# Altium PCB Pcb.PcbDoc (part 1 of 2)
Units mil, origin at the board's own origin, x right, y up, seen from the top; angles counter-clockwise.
Board outline 4875.67 x 2076.77 mil, 2 copper layers (Top Layer, Bottom Layer), stack 55.6 mil thick; 76 components, 37 nets, 162 pads, 28 vias.
Unrouted connection lines stored in the file: 67.
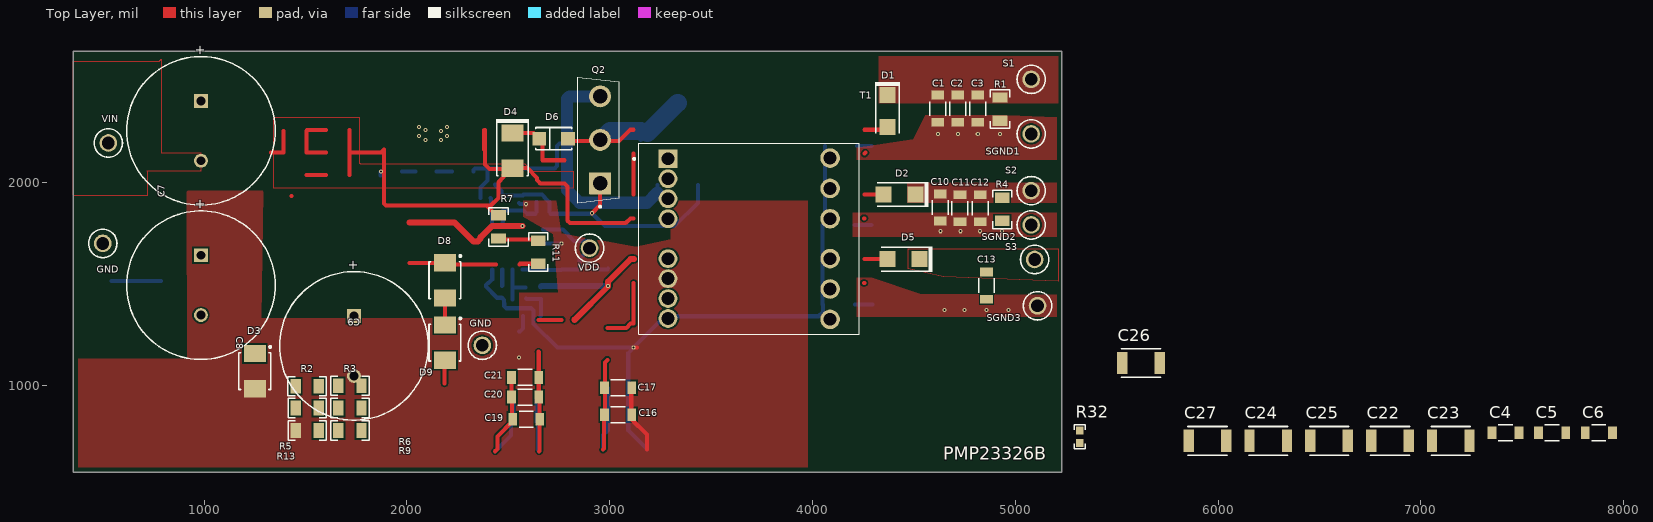
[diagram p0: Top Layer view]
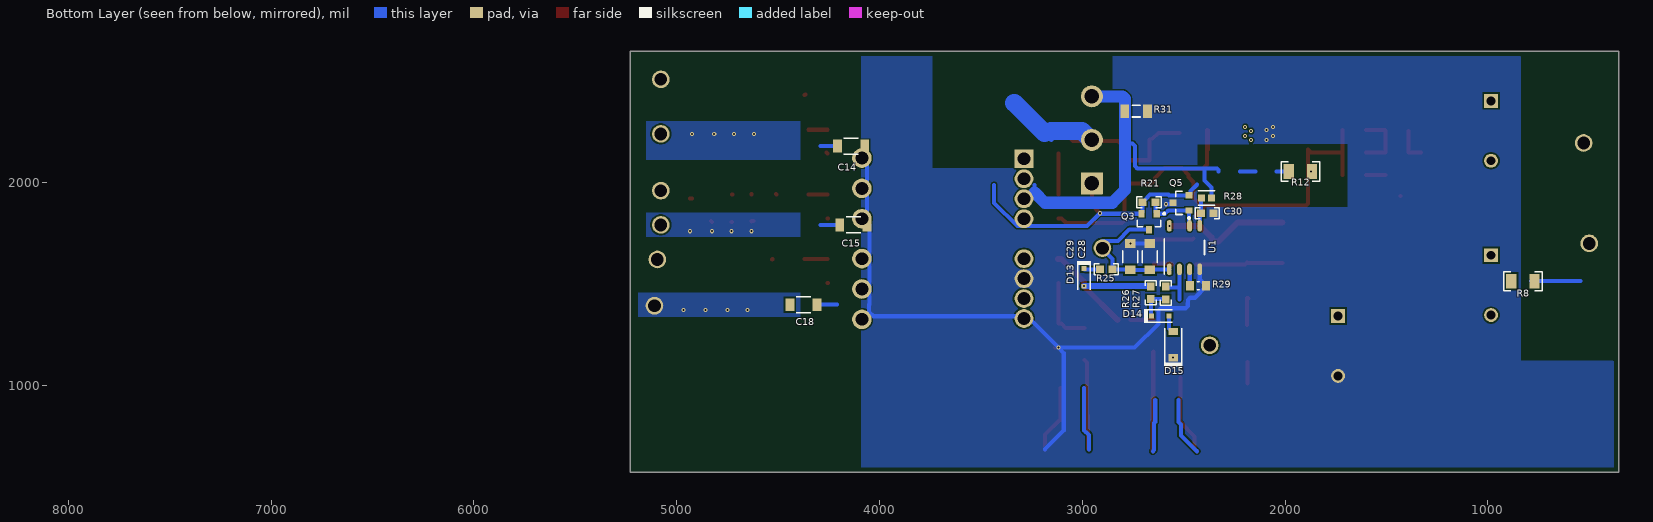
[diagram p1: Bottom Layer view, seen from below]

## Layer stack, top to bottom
Top Solder: solder mask 0.4, Solder Resist, Dk 3.5
Top Layer: signal copper 2.8
Dielectric 1: core 14.2, FR-4, Dk 4.8
Dielectric1: prepreg 21.6, Dk 4.2
Dielectric 2: core 14.2, FR-4, Dk 4.8
Bottom Layer: signal copper 2.8
Bottom Solder: solder mask 0.4, Solder Resist, Dk 3.5

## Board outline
354.33,570.87 5230,570.87 5230,2647.64 354.33,2647.64

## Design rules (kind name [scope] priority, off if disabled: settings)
AcuteAngle [All] p1: minimum=4.50000000000000E+0001 checktracksonly=FALSE
AssemblyTestPointUsage [All] p1: valid=2
BoardOutlineClearance BoardOutlineClearance_MountingHoles [OnCopper and InComponentClass('Mounting Holes')] p1: gap=39.37 ignorepadtopadclearanceinfootprint=FALSE
BoardOutlineClearance BoardOutlineClearance_Poly [OnCopper and IsPoly] p2: gap=25 ignorepadtopadclearanceinfootprint=FALSE
BoardOutlineClearance [OnCopper and Not InComponentClass('Logo') and not InComponentClass('FiducialMark') and not InRegion(1000,500,4000,800) and not InPoly] p3: gap=75 ignorepadtopadclearanceinfootprint=FALSE
Clearance [InNet('HV_plus') vs InNet('HV_minus')] p1: gap=140 ignorepadtopadclearanceinfootprint=TRUE
Clearance Clearance_3 [All] p2: gap=7.87 ignorepadtopadclearanceinfootprint=TRUE
Clearance Clearance_2 [InNet('SGND1') vs InNet('SGND2')] p3: gap=150 ignorepadtopadclearanceinfootprint=TRUE
Clearance Clearance_1 [InNet('SGND2') vs InNet('SGND3')] p4: gap=150 ignorepadtopadclearanceinfootprint=TRUE
Clearance Clearance_Keepouts [((IsTrack Or IsArc) And Not InPoly) And IsFree and IsKeepOut vs ((IsTrack Or IsArc) And Not InPoly) And IsFree and IsKeepOut] p5: gap=0 ignorepadtopadclearanceinfootprint=FALSE
Clearance Clearance_Poly [InPolygon] p6: gap=25 ignorepadtopadclearanceinfootprint=TRUE
Clearance Clearance_FiducialMark [IsKeepOut and InComponentClass('FiducialMark') vs IsPad and InComponentClass('FiducialMark')] p7: gap=0 ignorepadtopadclearanceinfootprint=FALSE
Clearance Clearance-pgnd-vin [InNet('PGND') vs InNet('NetC7_1')] p8: gap=120 ignorepadtopadclearanceinfootprint=TRUE
ComponentClearance ComponentClearance_MountingHoles_FiducialMarks [InComponentClass('Mounting Holes') vs InComponentClass('FiducialMark')] p1: gap=50 collisioncheckmode=3 verticalgap=10 showdistances=FALSE
ComponentClearance ComponentClearance_Shunt [InComponentClass('Header') vs InComponentClass('Shunt')] p2: gap=0 collisioncheckmode=3 verticalgap=0 showdistances=FALSE
ComponentClearance ComponentClearance_Logo [InComponentClass('Logo')] p3: gap=50 collisioncheckmode=3 verticalgap=10 showdistances=FALSE
ComponentClearance ComponentClearance_ScrewToNut [(HasFootprint('NY PMS 440 0025 PH')) vs (HasFootprint('Keystone_1902C'))] p4: gap=5 collisioncheckmode=3 verticalgap=10 showdistances=FALSE
ComponentClearance ComponentClearance_MountingHoles [InComponentClass('Mounting Holes')] p5: gap=250 collisioncheckmode=3 verticalgap=100000 showdistances=FALSE
ComponentClearance ComponentClearance_SmallPassives [HasFootprint('0201*') or HasFootprint('0402*') or HasFootprint('0508') or HasFootprint('0603*') or HasFootprint('0612') or HasFootprint('0805*') or HasFootprint('0815*') or HasFootprint('0830*') or HasFootprint('1206*') or HasFootprint('1210*') or HasFootprint('1808*') or HasFootprint('1812*') or HasFootprint('1825*') or HasFootprint('2010*') or HasFootprint('2220*') or HasFootprint('2225*') or HasFootprint('2512*') or HasFootprint('2728*') or HasFootprint('3518*') vs HasFootprint('0201*') or HasFootprint('0402*') or HasFootprint('0508') or HasFootprint('0603*') or HasFootprint('0612') or HasFootprint('0805*') or HasFootprint('0815*') or HasFootprint('0830*') or HasFootprint('1206*') or HasFootprint('1210*') or HasFootprint('1808*') or HasFootprint('1812*') or HasFootprint('1825*') or HasFootprint('2010*') or HasFootprint('2220*') or HasFootprint('2225*') or HasFootprint('2512*') or HasFootprint('2728*') or HasFootprint('3518*')] p6: gap=14.96 collisioncheckmode=3 verticalgap=10 showdistances=FALSE
ComponentClearance ComponentClearance_THtoSMT [IsThruComponent vs IsSMTComponent] p7: gap=40 collisioncheckmode=3 verticalgap=30 showdistances=FALSE
ComponentClearance ComponentClearance_THtoTH [IsThruComponent vs IsThruComponent] p8: gap=30 collisioncheckmode=3 verticalgap=30 showdistances=FALSE
ComponentClearance [All] p9: gap=30 collisioncheckmode=3 verticalgap=10 showdistances=FALSE
DiffPairsRouting [All] p1: maxlimit=100 minlimit=10 mostfreqgap=10 toplayer_minwidth=15 toplayer_maxwidth=15 toplayer_prefwidth=15 bottomlayer_minwidth=15 bottomlayer_maxwidth=15 bottomlayer_prefwidth=15 maxuncoupledlength=1000
FabricationTestPointUsage TestPointUsage [All] p1: valid=2 allowmultiple=FALSE
FabricationTestpoint Testpoint [All] p1: side=3 testpointundercomponent=TRUE minsize=40 maxsize=100 preferedsize=60 minholesize=0 maxholesize=40 preferedholesize=32 testpointgrid=1 allowsidetop=TRUE allowsidebottom=TRUE usegrid=TRUE gridtolerance=0.01
FanoutControl Fanout_LCC [IsLCC] p1: bgadir=Out bgaviamode=Centered fanoutstyle=Auto fanoutdirection=Alternating viagrid=1 // Fanout_LCC (Default Rule)
FanoutControl Fanout_BGA [IsBGA] p2: bgadir=Out bgaviamode=Centered fanoutstyle=Auto fanoutdirection=Alternating viagrid=1 // Fanout_BGA (Default Rule)
FanoutControl Fanout_Default [All] p4: bgadir=Out bgaviamode=Centered fanoutstyle=Auto fanoutdirection=Alternating viagrid=1 // Fanout_Default (Default Rule)
FanoutControl Fanout_Small [(CompPinCount < 5)] p5: bgadir=Out bgaviamode=Centered fanoutstyle=Auto fanoutdirection=OutThenIn viagrid=1 // Fanout_Small (Default Rule)
HoleSize [All] p1: absolutevalues=TRUE maxlimit=251 minlimit=7.87 maxpercent=80.000 minpercent=20.000
MinimumAnnularRing MinimumAnnularRing_ThermalPadVias [IsVia and InAnyComponent] p1: minimumring=5.91
MinimumAnnularRing [All] p2: minimumring=4.5
MinimumSolderMaskSliver MinimumSolderMaskSliver_Logo [InComponentClass('Logo') vs InComponentClass('Logo')] p1: minsoldermaskwidth=0.7
MinimumSolderMaskSliver [All] p2: minsoldermaskwidth=3.94
PlaneConnect [All] p1: planeconnectstyle=Direct reliefexpansion=10 reliefentries=4 reliefconductorwidth=10 reliefairgap=10
PolygonConnect [All] p1: connectstyle=Direct reliefconductorwidth=10 reliefentries=4 polygonreliefangle="90 Angle" airgapwidth=10
RoutingVias ThermalPadVias [IsVia and InAnyComponent] p1: holewidth=7.87 width=19.68 viastyle="Through Hole" minholewidth=7.87 minwidth=19.68 maxholewidth=12.99 maxwidth=23.62
RoutingVias [All] p2: holewidth=16 width=34 viastyle="Through Hole" minholewidth=7.87 minwidth=18 maxholewidth=40 maxwidth=65
SilkToBoardRegionClearance [Not ((IsComment or IsDesignator) And (Hide <> 'False')) and not InRegion(1000,500,4000,800)] p1:
SilkToSilkClearance SilkToSilkClearance_Pb-FreeLogo [(HasFootprint('Pb-Free_Overlay_Medium') OR HasFootprint('Pb-Free_Overlay_Small')) vs (HasFootprint('Pb-Free_Overlay_Medium') OR HasFootprint('Pb-Free_Overlay_Small'))] p1: silktosilkclearance=0
SilkToSilkClearance [All] p2: silktosilkclearance=3.94
SilkToSolderMaskClearance SilkToComponentPadClearance [(IsPad or IsFill or IsRegion) and InAnycomponent] p1: minsilkscreentomaskgap=5 clearancetoexposedcopper=TRUE
SilkToSolderMaskClearance "Silk to Solder Mask Opening" [All] p2: minsilkscreentomaskgap=3.94 clearancetoexposedcopper=FALSE
SolderMaskExpansion [All] p1: expansion=1.97 istentingtop=FALSE
UnRoutedNet [All] p1: checkbadconnections=TRUE
Width [All] p1: maxlimit=100 minlimit=6 preferedwidth=20 minimp=50.000000 maximp=50.000000 favimp=50.000000 checkconnectedcopper=TRUE
14 further rules are at their usual default settings.

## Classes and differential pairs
component class Schematic: C1 C2 C3 C7 C8 C9 C13 C14 C15 C16 C17 C18 C19 C20 C21 C25 C26 C27 C28 C29 C30 D1 D2 D3 D4 D5 D6 D8 D9 D13 D14 D15 Q2 Q3 Q5 R1 R2 R3 R4 R5 R6 R7 R8 R9 R11 R12 R13 R21 R25 R26 R27 R28 R29 R31 R32 S1 S2 S3 SGND1 SGND2 SGND3 T1 U1 VDD VIN

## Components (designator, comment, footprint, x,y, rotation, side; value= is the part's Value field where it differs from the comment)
C1 "UMJ316AB7225KLHT" 1206_180 4618.38,2364.32 r270 top value=2.2uF
C2 "UMJ316AB7225KLHT" 1206_180 4716.81,2364.32 r270 top value=2.2uF
C3 "UMJ316AB7225KLHT" 1206_180 4815.23,2364.32 r270 top value=2.2uF
C4 "UMJ316AB7225KLHT" 1206_180 7418,766 r0 top value=2.2uF
C5 "UMJ316AB7225KLHT" 1206_180 7648,766 r0 top value=2.2uF
C6 "UMJ316AB7225KLHT" 1206_180 7878,766 r0 top value=2.2uF
C7 "EEU-EE2G470S" EE_1800x2000 984.01,2255.18 r270 top value=47uF
C8 "EEU-EE2G470S" EE_1800x2000 984.01,1493.93 r270 top value=47uF
C9 "EEU-EE2G470S" EE_1800x2000 1738.47,1194.29 r270 top value=47uF
C10 "UMJ316AB7225KLHT" 1206_180 4630.46,1877.16 r270 top value=2.2uF
C11 "UMJ316AB7225KLHT" 1206_180 4727.49,1873.33 r270 top value=2.2uF
C12 "UMJ316AB7225KLHT" 1206_180 4827.31,1873.33 r270 top value=2.2uF
C13 "UMJ316AB7225KLHT" 1206_180 4858.36,1491.68 r270 top value=2.2uF
C14 "UMJ316AB7225KLHT" 1206_180 4140,2180 r180 bottom value=2.2uF
C15 "UMJ316AB7225KLHT" 1206_180 4128.74,1791.34 r180 bottom value=2.2uF
C16 "UMJ316AB7225KLHT" 1206_180 3041.34,855.41 r0 top value=2.2uF
C17 "UMJ316AB7225KLHT" 1206_180 3041.34,987.84 r0 top value=2.2uF
C18 "UMJ316AB7225KLHT" 1206_180 4374.9,1397.64 r180 bottom value=2.2uF
C19 "UMJ316AB7225KLHT" 1206_180 2588.56,832.67 r180 top value=2.2uF
C20 "UMJ316AB7225KLHT" 1206_180 2583.1,942.31 r180 top value=2.2uF
C21 "UMJ316AB7225KLHT" 1206_180 2583.1,1039.2 r180 top value=2.2uF
C22 "C4532X7R3D222K130KA" FP-C4532-130-MFG 6848,726 r0 top
C23 "C4532X7R3D222K130KA" FP-C4532-130-MFG 7148,726 r0 top
C24 "C4532X7R3D222K130KA" FP-C4532-130-MFG 6248,726 r0 top
C25 "C4532X7R3D222K130KA" FP-C4532-130-MFG 6548,726 r0 top
C26 "C4532X7R3D222K130KA" FP-C4532-130-MFG 5620,1110 r0 top
C27 "C4532X7R3D222K130KA" FP-C4532-130-MFG 5948,726 r0 top
C28 "" FP-CGA5L-0_3-0_1-MFG 2667.11,1634.48 r90 bottom
C29 "" FP-CGA5L-0_3-0_1-MFG 2763.13,1634.48 r90 bottom
C30 "CGA3E2NP01H101J080AA" 0603 2383.53,1848.64 r180 bottom value=100pF
D1 "MURA160T3G" SMA 4369.44,2352.36 r270 top value=600V
D2 "MURA160T3G" SMA 4429.13,1941.67 r180 top value=600V
D3 "SZ1SMB5956BT3G" ONSC-SMB-2-403A-03_H_V 1250,1070 r270 top
D4 "SMBJ100A-13-F" SMB 2520.8,2157.78 r270 top value=100V
D5 "MURA160T3G" SMA 4448.82,1622.13 r180 top value=600V
D6 "BYG23T-M3/TR" FP-SMA-MFG 2723.85,2216.63 r0 top
D8 "SZ1SMB5956BT3G" ONSC-SMB-2-403A-03_H_V 2187.57,1518.05 r270 top
D9 "SZ1SMB5956BT3G" ONSC-SMB-2-403A-03_H_V 2187.57,1210.63 r270 top
D13 "BAV20WS-TP" SOD-323 2991.61,1532.28 r270 bottom value=150V
D14 "BAV20WS-TP" SOD-323 2615.69,1341.92 r180 bottom value=150V
D15 "DDZ20CQ-7" SOD-123 2552.03,1200.79 r90 bottom value=20V
GND "5011" Keystone5011 500,1700 r90 top
GND "5011" Keystone5011 2371.72,1197.49 r0 top
Q2 "STW12N120K5" FP-STW12N120K5_TO-247-3-MFG 2944.88,2210.52 r180 top
Q3 "MMBT3904LT1G" ONSC-SOT-23-3-318-08_V 2670.89,1806.91 r270 bottom
Q5 "MMBT2907ALT3G" ONSC-SOT-23-3-318-08_V 2512.66,1899.83 r0 bottom
R1 "ERJ-8ENF1002V" 1206 4924.75,2362.2 r90 top value=10.0k
R2 "CRCW1206470KJNEA" 1206 1507.87,995.34 r0 top value=470k
R3 "ERJ-8ENF1002V" 1206 1718.78,998.27 r0 top value=10.0k
R4 "ERJ-8ENF1002V" 1206 4935.58,1867.86 r90 top value=10.0k
R5 "CRCW1206470KJNEA" 1206 1508.19,887.53 r0 top value=470k
R6 "CRCW1206300KJNEA" 1206 1718.78,887.53 r0 top value=300k
R7 "CRCW1206300KJNEA" 1206 2451.52,1780.97 r90 top value=300k
R8 "CRCW1206470KJNEA" 1206 826.77,1513.61 r0 bottom value=470k
R9 "CRCW1206300KJNEA" 1206 1718.78,777.04 r0 top value=300k
R11 "CRCW1206470KJNEA" 1206 2647.26,1656.8 r90 top value=470k
R12 "CRCW1206470KJNEA" 1206 1924.21,2054.7 r180 bottom value=470k
R13 "CRCW1206470KJNEA" 1206 1508.19,777.04 r0 top value=470k
R21 "RMCF0603ZT0R00" 0603 2670.89,1903.52 r0 bottom value=0
R25 "RMCF0603ZT0R00" 0603 2881.91,1572.07 r180 bottom value=0
R26 "ERJ3EKF5601V" 0603 2662.19,1456.33 r90 bottom value=5.60k
R27 "ERA-3AEB3742V" 0603 2588.05,1455.35 r270 bottom value=37.4k
R28 "1.2k" FP-ERA3A-IPC_C 2387.46,1923.41 r180 bottom
R29 "332k" FP-RG1608-MFG 2428.8,1490.49 r0 bottom
R31 "1.5" RESC3216X70X50NL05T20 2734.63,2351.9 r0 bottom
R32 "CRCW060313K3FKEA" 0603 5318,746 r90 top value=13.3k
S1 "5010" Keystone5010 5078.74,2509.08 r0 top
S2 "5010" Keystone5010 5078.74,1960 r0 top
S3 "5010" Keystone5010 5095.81,1620.72 r0 top
SGND1 "5011" Keystone5011 5078.74,2240 r0 top
SGND2 "5011" Keystone5011 5078.74,1791.34 r0 top
SGND3 "5011" Keystone5011 5110,1392.41 r0 top
T1 "750320469" FP-750320469_PTH14-MFG 3687.32,1723.17 r0 top
U1 "UCC28730QDRQ1" D0007A_N 2495.73,1679.36 r90 bottom
VDD "5010" Keystone5010 2900.61,1676.48 r0 top
VIN "5010" Keystone5010 527.33,2195.17 r90 top

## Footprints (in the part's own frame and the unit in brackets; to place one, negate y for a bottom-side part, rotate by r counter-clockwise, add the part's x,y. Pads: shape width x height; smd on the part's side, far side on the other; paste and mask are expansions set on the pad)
0603 [mm] "0603 from SM-752 data"
  rect 1x0.95 smd: 1(-0.8,0) 2(0.8,0)
  silkscreen extent -1.52,-0.69 1.52,0.69, body extent -0.87,-0.47 0.87,0.47, height 1
1206 [mm] "1206 from SM-752 data"
  rect 1.3x1.85 smd: 1(-1.45,0) 2(1.45,0)
  silkscreen extent -2.4,-1.21 2.4,1.21, body extent -1.7,-0.9 1.7,0.9, height 1.35
1206_180 [mm] "1206_180"
  rect 1.1x1.6 smd: 1(-1.7,0) 2(1.7,0)
  silkscreen extent -0.9,-1 0.9,1, body extent -1.75,-0.95 1.75,0.95, height 1.8
D0007A_N [mm] "SOIC, 7-Leads, Body 4.9x3.9mm, Pitch 1.27mm, IPC Medium Density"
  oval 1.45x0.6 smd: 1(-2.725,1.905) 2(-2.725,0.635) 3(-2.725,-0.635) 4(-2.725,-1.905) 5(2.725,-1.905) 6(2.725,-0.635) 8(2.725,1.905)
  silkscreen extent -3.32,-2.5 1.1,2.52, body extent -3.01,-2.45 3.01,2.45, height 1.75
EE_1800x2000 [mm] "PANASONIC"
  rect 1.75x1.75 hole 1.1: 1(-3.75,0)
  round 1.75 hole 1.1: 2(3.75,0)
  silkscreen extent -9.3,-9.3 9.3,9.3, body extent -9.18,-9.23 9.22,9.24, height 22.01
FP-750320469_PTH14-MFG [mm]
  rrect4% 2.35x2.35 hole 1.6 paste-1000 mask+0: 1(-10.15,10)
  round 2.35 hole 1.6 paste-1000 mask+0: 2(-10.15,7.5) 3(-10.15,5) 4(-10.15,2.5) 5(-10.15,-2.5) 6(-10.15,-5) 7(-10.15,-7.5) 8(-10.15,-10)
  round 2.45 hole 1.6 paste-1000 mask+0: 9(10.15,-10.1) 10(10.15,-6.3) 11(10.15,-2.5) 12(10.15,2.5) 13(10.15,6.3) 14(10.15,10.1)
  silkscreen extent -14.51,-11.95 13.79,11.95, body extent -13.89,-12.05 13.89,12.05, height 0.25
FP-C4532-130-MFG [mm]
  rect 1.3x2.8 smd paste+0 mask+0: 1(-2.35,0) 2(2.35,0)
  silkscreen extent -2.45,-1.8 2.45,1.8, body extent -3.1,-1.9 3.1,1.9, height 0.25
FP-CGA5L-0_3-0_1-MFG [mm]
  rect 1.1x1.35 smd paste+0 mask+0: 1(-1.65,0) 2(1.65,0)
  silkscreen extent -0.72,-0.95 0.72,0.95, body extent -1.6,-0.76 1.6,0.84, height 1.9
FP-ERA3A-IPC_C [mil]
  rect 33.66x35.68 smd paste+0 mask+0: 1(-24.63,0) 2(24.63,0)
  silkscreen extent -41,-35 41,35, body extent -31,-16 31,16, height 22
FP-RG1608-MFG [mm]
  rect 1x1.2 smd paste+0 mask+0: 1(-1,0) 2(1,0)
  silkscreen extent -0.13,-0.5 0.13,0.5, body extent -0.8,-0.4 0.8,0.4, height 0.5
FP-SMA-MFG [mm]
  rect 1.7x1.68 smd paste+0 mask+0: 1(-1.79,0) 2(1.79,0)
  silkscreen extent -2.25,-1.4 2.25,1.4, body extent -2.74,-1.5 2.74,1.5, height 0.25
FP-STW12N120K5_TO-247-3-MFG [mm]
  rrect4% 2.75x2.75 hole 1.8 paste-1000 mask+0: 1(-0.2,5.45)
  round 2.75 hole 1.8 paste-1000 mask+0: 2(-0.2,0) 3(-0.2,-5.45)
  silkscreen extent -2.58,-7.88 2.58,8.5, body extent -2.68,-7.98 2.68,7.98, height 0.25
Keystone5010 [mil] "Keystone Multipurpose loops"
  round 87 hole 63: 1(0,0)
  silkscreen extent -70,-70 70,70, body extent -63,-63 63,62, height 319
Keystone5011 [mil] "Keystone Multipurpose loops"
  round 87 hole 63: 1(0,0)
  silkscreen extent -70,-70 70,70, body extent -63,-63 63,62, height 319
ONSC-SMB-2-403A-03_H_V [mil] "Molded, 2-Leads, Body 4.6x3.95mm"
  rect 85x107.99 smd: 1(-87.01,0) 2(87.01,0)
  silkscreen extent -125,-79 91,81, body extent -91,-78 91,78, height 95
ONSC-SOT-23-3-318-08_V [mm] "SOT23, 3-Leads, Body 2.92x1.3mm, Pitch 0.95mm"
  rect 0.9x0.8 smd: 1(-1,0.95) 2(-1,-0.95) 3(1,0)
  silkscreen extent -1.12,-1.46 0.65,2.02, body extent -0.65,-1.46 0.65,1.46, height 1.11
RESC3216X70X50NL05T20 [mm] "Chip Resistor, 2-Leads, Body 3.20x1.60mm, IPC Medium Density"
  rect 1.1x1.65 smd: 1(-1.425,0) 2(1.425,0)
  silkscreen extent -0.5,-0.72 0.5,0.72, body extent -1.63,-0.82 1.62,0.82, height 0.7
SMA [mm] "Molded Diode, 2-Leads, Body 4.3x2.6mm, IPC Medium Density, based on OnSemi component dimensions and land pattern"
  rect 2x2 smd: 1(-2,0) 2(2,0)
  silkscreen extent -3.66,-1.57 2.79,1.57, body extent -2.6,-1.3 2.6,1.3, height 2.42
SMB [mil] "Molded Diode, 2-Leads, Body 5.4x3.6mm, IPC Medium Density, based on OnSemi component dimensions"
  rect 85x107.99 smd: 1(-87.01,0) 2(87.01,0)
  silkscreen extent -155,-82 125,82, body extent -106,-71 106,71, height 91
SOD-123 [mm] "On Semi recommended land pattern"
  rect 0.915x1.22 smd: 1(-1.637,0) 2(1.637,0)
  silkscreen extent -2.74,-1.17 2.03,1.17, body extent -1.93,-0.9 1.93,0.9, height 1.35
SOD-323 [mm] "NXP recommended land pattern"
  rect 0.6x0.6 smd paste-0.05: 1(-1.1,0) 2(1.1,0)
  silkscreen extent -2.06,-0.86 1.53,0.86, body extent -1.3,-0.67 1.3,0.68, height 1.1

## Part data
C1 C2 C3 C4 C5 C6 C10 C11 C12 C13 C14 C15 C16 C17 C18 C19 C20 C21: library part CMP-0080745-1, "CAP, CERM, 2.2 µF, 50 V,+/- 10%, X7R, AEC-Q200 Grade 1, 1206", Cap_Case=1206, Manufacturer="Taiyo Yuden", Supplier Part Number 1=587-4271-1-ND, TempCo=X7R, Tolerance_%=10%, Value2=50V, ValueDisplayed=2.2µF
C7 C8 C9: library part CMP-0010026-1, "CAP, AL, 47 uF, 400 V, +/- 20%, TH", Cap_Case=18x20, Manufacturer=Panasonic, Supplier Part Number 1=P13667-ND, Tolerance_%=20%, Value1=Unknown, Value2=400V, ValueDisplayed=47uF
C22 C23 C24 C25 C26 C27: library part CMP-08246-007253-1, "CAP CER 2200PF 2KV X7R 1812", Capacitance=2.2nF, Case Code (Imperial)=1812, Case Code (Metric)=4532, Dielectric=X7R, Max Operating Temperature=125°C, Min Operating Temperature=-55°C, Package Quantity=1, Resistor Type=Ceramic, Tolerance=10%, Voltage=2kV
C28 C29: library part CMP-08246-001891-1, "Cap Ceramic 10uF 50V X7R 10% Pad SMD 1206 +125°C Automotive T/R", Capacitance=10uF, Case Code (Imperial)=1206, Case Code (Metric)=3216, Max Operating Temperature=125°C, Min Operating Temperature=-55°C, Ratings=AEC-Q200, Tolerance=10%, Voltage Rating=50V
C30: library part CMP-0007075-4, "CAP, CERM, 100 pF, 50 V, +/- 5%, C0G/NP0, AEC-Q200 Grade 0, 0603", Cap_Case=0603, Manufacturer=TDK, Supplier Part Number 1=445-12386-1-ND, TempCo=C0G/NP0, Tolerance_%=5%, Value1=Unknown, Value2=50V, ValueDisplayed=100pF
D1 D2 D5: library part CMP-0029033-2, "Diode, Ultrafast, 600 V, 1 A, AEC-Q101, SMA", Manufacturer="ON Semiconductor", Value1=1A, Value2=1.05V
D3 D8 D9: library part CMP-1060-00171-1, "3 W Zener Voltage Regulator, 2-Pin SMB, Pb-Free, Tape and Reel", Manufacturer="On Semiconductor"
D4: library part CMP-0005571-3, "Diode, TVS, Uni, 100 V, 162 Vc, SMB", Manufacturer="Diodes Inc.", Value1=600W
D6: library part CMP-02540-000071-1, "DIODE AVALANCHE 1300V 1A DO214AC", Average Rectified Current=1A, Case/Package=SMA, Forward Voltage=1.74V, Max Forward Surge Current (Ifsm)=18A, Max Operating Temperature=150°C, Max Power Dissipation=800mW, Max Repetitive Reverse Voltage (Vrrm)=1.3kV, Max Reverse Current=5uA, Min Operating Temperature=-55°C, Package Quantity=1800, Zener Voltage=200V
D13 D14: library part CMP-0029044-2, "Diode, P-N, 150 V, 0.2 A, SOD-323", Manufacturer="Micro Commercial Components", Value1=0.2A, Value2=1.25V
D15: library part CMP-0085147-1, "Diode, Zener, 20 V, 500 mW, AEC-Q101, SOD-123", Manufacturer="Diodes Inc.", Power_W=500mW, Value1=0.5W
GND GND SGND1 SGND2 SGND3: library part CMP-0055148-1, "Test Point, Multipurpose, Black, TH", Color=Black, Manufacturer=Keystone, Supplier Part Number 1=36-5011-ND
Q2: library part CMP-0036771-1, "N-Channel 1200 V 12A (Tc) 250W (Tc) Through Hole TO-247-3", Digikey Part Number=497-15446-5-ND, Drain To Source Breakdown Voltage=1200V, Input Capacitace At Vds="1370pF @ 100V", Manufacturer=STMicroelectronics, Mouser Part Number=511-STW12N120K5, Operating Temperature Range="-55°C to +150°C", Power_W=250W, Pulse Drain Current=48A
Q3: library part CMP-1048-00631-1, "General Purpose Transistor, NPN Silicon, 3-Pin SOT-23, Pb-Free, Tape and Reel", Manufacturer="On Semiconductor"
Q5: library part CMP-1048-00587-1, "General Purpose Transistor, PNP Silicon, 3-Pin SOT-23, Pb-Free, Tape and Reel", Manufacturer="On Semiconductor"
R1 R3 R4: library part CMP-0017284-3, "RES, 10.0 k, 1%, 0.25 W, AEC-Q200 Grade 0, 1206", Manufacturer=Panasonic, Power_W=250mW, Supplier Part Number 1=P10.0KFCT-ND, TempCo="100 ppm/C", Tolerance_%=1%, Value2=0.25W, Value_Code=10k0, ValueDisplayed=10.0k
R2 R5 R8 R11 R12 R13: library part CMP-0018684-3, "RES, 470 k, 5%, 0.25 W, AEC-Q200 Grade 0, 1206", Manufacturer=Vishay-Dale, Power_W=250mW, Supplier Part Number 1=541-470KECT-ND, TempCo="200 ppm/C", Tolerance_%=5%, Value2=0.25W, Value_Code=470k
R6 R7 R9: library part CMP-0018652-3, "RES, 300 k, 5%, 0.25 W, AEC-Q200 Grade 0, 1206", Manufacturer=Vishay-Dale, Power_W=250mW, Supplier Part Number 1=541-300KECT-ND, TempCo="200 ppm/C", Tolerance_%=5%, Value2=0.25W, Value_Code=300k
R21 R25: library part CMP-0023343-3, "RES, 0, 1%, 0.1 W, AEC-Q200 Grade 0, 0603", Manufacturer="Stackpole Electronics Inc", Power_W=100mW, Supplier Part Number 1=RMCF0603ZT0R00CT-ND, TempCo=ppm/C, Tolerance_%=1%, Value2=0.1W, Value_Code=0
R26: library part CMP-0078666-1, "RES, 5.60 k, 1%, 0.1 W, AEC-Q200 Grade 0, 0603", Manufacturer=Panasonic, Power_W=100mW, Supplier Part Number 1=P5.60KHCT-ND, TempCo="100 ppm/C", Tolerance_%=1%, Value2=0.1W, Value_Code=5k60, ValueDisplayed=5.60k
R27: library part CMP-0860903-1, "RES, 37.4 k, 0.1%, 0.1 W, AEC-Q200 Grade 0, 0603", Manufacturer=Panasonic, Power_W=100mW, TempCo="25 ppm/C", Tolerance_%=0.1%, Value2=0.1W, Value_Code=37k4, ValueDisplayed=37.4k
R28: library part CMP-2000-00897-2, "RES SMD 1.2K OHM 0.1% 1/10W 0603", Case Code (Imperial)=0603, Case Code (Metric)=1608, Max Operating Temperature=155°C, Max Power Dissipation=100mW, Min Operating Temperature=-55°C, Package Quantity=1, Resistance=1.2kR, Resistance Tolerance=0.1%, Resistor Type="Thin Film", Temperature Coefficient=25ppm/°C, Voltage Rating=75V
R29: library part CMP-2000-02200-2, "Automotive Metal Thin Film Chip Resistor, 0603, 332kΩ, 0.1%, 25ppm/°C, 0.1W, 100V", Case Code (Imperial)=0603, Case Code (Metric)=1608, Max Operating Temperature=155°C, Max Power Dissipation=100mW, Min Operating Temperature=-55°C, Package Quantity=5000, Power Rating=62.5mW, Resistance=332kR, Resistor Type="Thin Film", Temperature Coefficient=25ppm/°C, Tolerance=0.1%, Voltage Rating=75V
R31: library part CMP-2003-00683-1, Manufacturer=Panasonic, Part Number=ERJ-8RQF1R5V
R32: library part CMP-0022043-4, "RES, 13.3 k, 1%, 0.1 W, AEC-Q200 Grade 0, 0603", Manufacturer=Vishay-Dale, Power_W=100mW, Supplier Part Number 1=541-13.3KHCT-ND, TempCo="100 ppm/C", Tolerance_%=1%, Value2=0.1W, Value_Code=13k3, ValueDisplayed=13.3k
S1 S2 S3 VDD VIN: library part CMP-0055147-1, "Test Point, Multipurpose, Red, TH", Color=Red, Manufacturer=Keystone, Supplier Part Number 1=36-5010-ND
T1: library part CMP-0120025-1, "TRANSFORMER", Frequency_Fixed=75kHz, Manufacturer="Wurth Electronics", Operating Temperature Range="-40°C to +125°C", Voltage_Isolation_Vrms=6.9kV
U1: library part CMP-0065056-3, "Zero Standby PSR Flyback Controller with CVCC and Wake-Up Monitoring, Automotive, D0007A (SOIC-7)", Alternate Manufacturer="Texas Instruments"

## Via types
v1: diameter 20, hole 10, Top Layer to Bottom Layer, 28 vias

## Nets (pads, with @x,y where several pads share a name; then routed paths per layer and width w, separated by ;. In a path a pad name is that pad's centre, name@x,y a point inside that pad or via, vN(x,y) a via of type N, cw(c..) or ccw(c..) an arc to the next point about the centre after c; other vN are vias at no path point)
Aux: D13.2 R26.2 T1.5 | length 760.2
  Top Layer w30: 2826.37,1323.22 2827.36,1323.22 2991.61,1487.47 v1(2991.61,1488.97) 2991.61,1511.71 3102.68,1622.78 3118.43,1622.78
  Bottom Layer w30: R26.2@2662.19,1487.83 2663.33,1488.97 v1(2991.61,1488.97)
HV: D8.1 R9.1 U1.8 | length 1065.5
  Top Layer w20: 2011.7,1603.31 2185.83,1603.31 D8.1@2187.57,1605.05 2196.65,1595.97 2338.25,1595.97 2439.55,1595.97 2439.95,1596.37
  Top Layer w30: 2011.7,1803.31 2234.26,1803.31 2327.42,1710.15 2349.08,1710.15 2363.7,1724.77 2363.7,1730.42 2419.92,1786.64 v1(2570.73,1786.64)
NetC1_1: C1.1 C2.1 C3.1 C4.1 C5.1 C6.1 D1.1 R1.2 S1.1 | length 5.4
  Top Layer w20: D1.1@4366.09,2434.45 D1.1@4369.44,2431.1 D1.1@4369.87,2431.54
NetC7_2: C7.2 C8.1 R5.1 R8.2
NetC8_2: C8.2 C9.1 R11.1 R12.2 | length 94.5
  Top Layer w20: 2554.12,1596.37 2557.46,1599.71 R11.1@2647.26,1599.71
NetC10_1: C10.1 C11.1 C12.1 C13.1 C14.1 C15.1 D2.1 R3.2 S2.1 | length 177.3
  Top Layer w20: D2.1@4508.41,1941.13 D2.1@4507.87,1941.67 D2.1@4510.29,1944.09 ; C10.1@4630.46,1944.09 C10.1@4632.37,1942.17 ; C11.1@4725.57,1942.17 C11.1@4727.49,1940.26 ; 4924.75,1921.99 4935.58,1921.99
  Bottom Layer w20: C15.1@4207.48,1791.34 4289.92,1791.34 4291.26,1790 ; C14.1@4218.74,2180 4291.26,2180
NetC16_1: C16.1 C17.1 C18.1 C19.1 C20.1 C21.1 D5.1 R4.2 S3.1 | length 948.6
  Top Layer w20: 2648.73,1165.74 2650.03,1164.44 C21.1@2650.03,1039.2 C20.1@2650.03,942.31 2652.76,939.58 2652.76,835.4 C19.1@2655.49,832.67 2653.75,830.92 2653.75,676.59 2652,674.84 ; 2966.58,682.97 2971.48,687.87 2971.48,850.51 2976.38,855.41 2976.38,987.84 2976.38,1113.64 2988.18,1125.45 ; D5.1@4527.56,1622.13 D5.1@4528.97,1620.72
NetC22_2: C22.2 C23.1
NetC24_2: C24.2 C25.1
NetC26_2: C26.2 C27.1
NetC30_1: C30.1 R28.1 U1.5 | length 140.3
  Bottom Layer w20: R28.1@2412.1,1923.41 2413.56,1921.94 2413.56,1850.1 C30.1@2415.02,1848.64 2420.04,1843.63 2420.04,1787.33 U1.5@2420.73,1786.64
NetD1_2: D1.2 T1.9 | length 94.2
  Top Layer w20: 4256.22,2260.57 D1.2@4350.39,2260.57
NetD2_2: D2.2 T1.11 | length 94.2
  Top Layer w20: 4256.22,1941.67 D2.2@4350.39,1941.67
NetD3_1: D3.1 D9.2 | length 104.8
  Top Layer w20: 2185.04,1009.35 D9.2@2185.04,1114.18
NetD4_1: D4.1 D6.1
NetD5_2: D5.2 T1.13 | length 114.1
  Top Layer w20: 4256.22,1622.78 4369.44,1622.78 D5.2@4370.08,1622.13
NetD6_2: D6.2 Q2.2 T1.2 | length 831.9
  Top Layer w20: D6.2@2800.32,2213.31 D6.2@2816.12,2197.52 ; D6.2@2807.66,2204.72 2952.76,2204.72 3046.83,2204.72 3102.68,2260.57 3118.43,2260.57
  Bottom Layer w20: 3153.11,2210.79 3186.42,2244.09
  Bottom Layer w90: Q2.2@2952.76,2210.52 2957.7,2210.52 3001.11,2253.94 3153.11,2253.94 ; 3186.42,2244.09 3335.04,2392.72
NetD8_2: D8.2 D9.1 | length 140.6
  Top Layer w20: D9.1@2187.57,1297.64 2187.57,1422.71 2181.5,1428.77 2183.77,1431.04 D8.2@2187.57,1431.04
NetD13_1: D13.1 R25.1 | length 79.7
  Bottom Layer w20: R25.1@2913.41,1572.07 2988.1,1572.07 D13.1@2991.61,1575.58
NetD14_1: D14.1 R26.1 R27.2 | length 158.7
  Bottom Layer w20: R27.2@2588.05,1428.77 2590.02,1426.8 2660.22,1426.8 2660.6,1426.43 2660.6,1343.52 D14.1@2659,1341.92
NetD14_2: D14.2 D15.2 | length 88.6
  Bottom Layer w20: D15.2@2552.03,1265.26 2558.03,1265.26 2572.39,1279.61 D14.2@2572.39,1341.92
NetQ2_1: Q2.1 Q3.2 Q5.2 R21.2 | length 1429.7
  Top Layer w20: v1(2913.09,1848.64) 2952.76,1888.3 Q2.1@2952.76,1995.96
  Bottom Layer w20: 2433.72,1991.18 2433.72,1989.21 2465.57,1957.36 2465.57,1942.98 2471.32,1937.23 Q5.2@2473.29,1937.23 2572.31,1937.23 2575.18,1940.1 2666.48,1940.1 2678.55,1928.02 2678.55,1926.36 R21.2@2701.4,1903.52 ; R21.2@2702.38,1903.52 2702.38,1854.16 2708.29,1848.25 Q3.2@2708.29,1846.28 2910.73,1846.28 v1(2913.09,1848.64) 2976.17,1785.56 3320.48,1785.56 3435.04,1900.12 3435.04,1988.19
